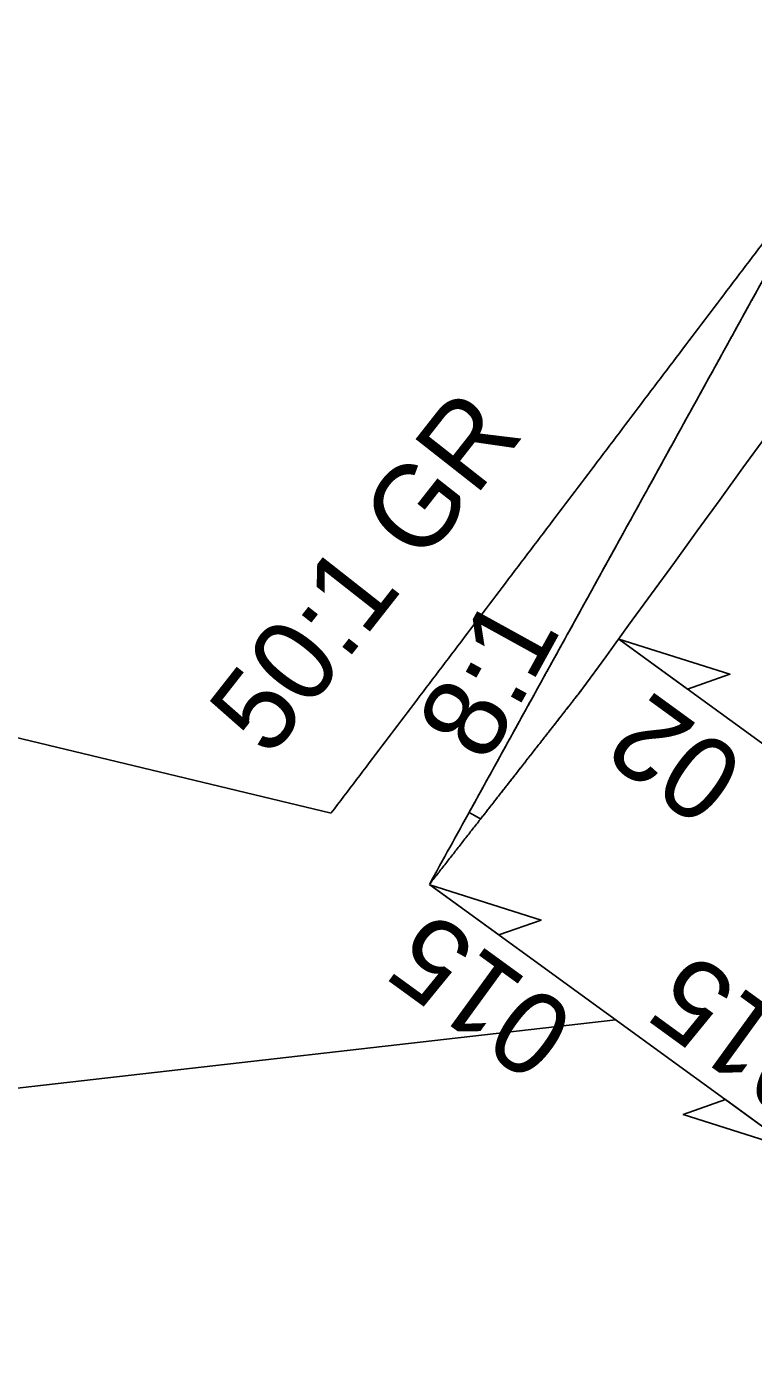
# Model space of a CAD drawing. Extents: x 1183930 to 1185370, y 573068 to 574871.
# Drawn here: x 1184207.5 to 1184246.9, y 573632.6 to 573704.9 of the extents above; entities that cross this region are included whole.
import ezdxf

# ---------------------------------------------------------------- set-up
doc = ezdxf.new("R2010")
doc.units = 0
for name, color, linetype in [('E_NCDOT_Vertical_Profile_Ground_Line', 7, 'Continuous'), ('P_NCDOT_Horizontal_Alignment', 7, 'Continuous'), ('P_NCDOT_Horizontal_Alignment_Tick_Large', 7, 'Continuous'), ('PC_COLUMN', 7, 'Continuous'), ('PC_OBJECT', 7, 'Continuous'), ('PC_PADFOOTING', 7, 'Continuous'), ('PC_SLAB', 7, 'Continuous'), ('PS_HATCH', 7, 'Continuous')]:
    doc.layers.add(name, color=color, linetype=linetype)

msp = doc.modelspace()

# ---------------------------------------------------------------- linework, layer by layer
at = {"layer": 'E_NCDOT_Vertical_Profile_Ground_Line'}
msp.add_open_spline([(1184229.343, 573658.378), (1184229.712, 573659.047), (1184230.451, 573660.384), (1184231.559, 573662.391), (1184232.666, 573664.397), (1184233.774, 573666.404), (1184234.881, 573668.41), (1184235.989, 573670.417), (1184237.096, 573672.423), (1184238.203, 573674.43), (1184239.311, 573676.436), (1184240.418, 573678.443), (1184241.525, 573680.45), (1184242.632, 573682.456), (1184243.739, 573684.463), (1184244.846, 573686.47), (1184245.953, 573688.477), (1184247.06, 573690.483), (1184248.166, 573692.49), (1184249.273, 573694.497), (1184250.379, 573696.504), (1184251.117, 573697.842), (1184251.486, 573698.511)], degree=3, dxfattribs=at)
msp.add_open_spline([(1184229.343, 573658.378), (1184229.712, 573659.047), (1184230.451, 573660.384), (1184231.559, 573662.391), (1184232.666, 573664.397), (1184233.774, 573666.404), (1184234.881, 573668.41), (1184235.989, 573670.417), (1184237.096, 573672.423), (1184238.203, 573674.43), (1184239.311, 573676.436), (1184240.418, 573678.443), (1184241.525, 573680.45), (1184242.632, 573682.456), (1184243.739, 573684.463), (1184244.846, 573686.47), (1184245.953, 573688.477), (1184247.06, 573690.483), (1184248.166, 573692.49), (1184249.273, 573694.497), (1184250.379, 573696.504), (1184251.117, 573697.842), (1184251.486, 573698.511)], degree=3, dxfattribs=at)
msp.add_open_spline([(1184229.343, 573658.378), (1184229.712, 573659.047), (1184230.451, 573660.384), (1184231.559, 573662.391), (1184232.666, 573664.397), (1184233.774, 573666.404), (1184234.881, 573668.41), (1184235.989, 573670.417), (1184237.096, 573672.423), (1184238.203, 573674.43), (1184239.311, 573676.436), (1184240.418, 573678.443), (1184241.525, 573680.45), (1184242.632, 573682.456), (1184243.739, 573684.463), (1184244.846, 573686.47), (1184245.953, 573688.477), (1184247.06, 573690.483), (1184248.166, 573692.49), (1184249.273, 573694.497), (1184250.379, 573696.504), (1184251.117, 573697.842), (1184251.486, 573698.511)], degree=3, dxfattribs=at)
at = {"layer": 'P_NCDOT_Horizontal_Alignment'}
msp.add_line((1184229.343, 573658.378), (1184249.41, 573643.786), dxfattribs=at)
msp.add_arc((1124762.272, 616900.028), 73527.16, 323.98763727, 324.09287436, dxfattribs=at)
msp.add_arc((1124762.272, 616900.028), 73527.16, 323.98763727, 324.09287436, dxfattribs=at)
msp.add_open_spline([(1184229.343, 573658.378), (1184229.482, 573658.555), (1184229.759, 573658.91), (1184230.176, 573659.441), (1184230.592, 573659.973), (1184231.008, 573660.505), (1184231.424, 573661.037), (1184231.841, 573661.568), (1184232.257, 573662.1), (1184232.673, 573662.632), (1184233.089, 573663.164), (1184233.506, 573663.695), (1184233.922, 573664.227), (1184234.338, 573664.759), (1184234.754, 573665.291), (1184235.17, 573665.823), (1184235.587, 573666.354), (1184236.003, 573666.886), (1184236.419, 573667.418), (1184236.835, 573667.95), (1184237.252, 573668.482), (1184237.529, 573668.836), (1184237.668, 573669.014)], degree=3, dxfattribs=at)
msp.add_open_spline([(1184229.343, 573658.378), (1184229.482, 573658.555), (1184229.759, 573658.91), (1184230.176, 573659.441), (1184230.592, 573659.973), (1184231.008, 573660.505), (1184231.424, 573661.037), (1184231.841, 573661.568), (1184232.257, 573662.1), (1184232.673, 573662.632), (1184233.089, 573663.164), (1184233.506, 573663.695), (1184233.922, 573664.227), (1184234.338, 573664.759), (1184234.754, 573665.291), (1184235.17, 573665.823), (1184235.587, 573666.354), (1184236.003, 573666.886), (1184236.419, 573667.418), (1184236.835, 573667.95), (1184237.252, 573668.482), (1184237.529, 573668.836), (1184237.668, 573669.014)], degree=3, dxfattribs=at)
at = {"layer": 'P_NCDOT_Horizontal_Alignment_Tick_Large'}
msp.add_open_spline([(1184224.019, 573662.249), (1184224.477, 573662.853), (1184225.393, 573664.061), (1184226.767, 573665.874), (1184228.141, 573667.687), (1184229.515, 573669.5), (1184230.888, 573671.313), (1184232.262, 573673.126), (1184233.635, 573674.939), (1184235.009, 573676.752), (1184236.382, 573678.565), (1184237.756, 573680.378), (1184239.129, 573682.191), (1184240.502, 573684.004), (1184241.875, 573685.817), (1184243.248, 573687.63), (1184244.621, 573689.444), (1184245.994, 573691.257), (1184247.367, 573693.07), (1184248.74, 573694.884), (1184250.113, 573696.697), (1184251.028, 573697.906), (1184251.486, 573698.511)], degree=3, dxfattribs=at)
msp.add_open_spline([(1184224.019, 573662.249), (1184224.477, 573662.853), (1184225.393, 573664.061), (1184226.767, 573665.874), (1184228.141, 573667.687), (1184229.515, 573669.5), (1184230.888, 573671.313), (1184232.262, 573673.126), (1184233.635, 573674.939), (1184235.009, 573676.752), (1184236.382, 573678.565), (1184237.756, 573680.378), (1184239.129, 573682.191), (1184240.502, 573684.004), (1184241.875, 573685.817), (1184243.248, 573687.63), (1184244.621, 573689.444), (1184245.994, 573691.257), (1184247.367, 573693.07), (1184248.74, 573694.884), (1184250.113, 573696.697), (1184251.028, 573697.906), (1184251.486, 573698.511)], degree=3, dxfattribs=at)
at = {"layer": 'PC_COLUMN'}
for points in [[(1184239.608, 573671.682), (1184245.637, 573669.771), (1184243.348, 573668.962)], [(1184229.374, 573658.354), (1184235.403, 573656.443), (1184233.115, 573655.634)], [(1184249.137, 573643.985), (1184243.108, 573645.896), (1184245.396, 573646.705)]]:
    msp.add_lwpolyline(points, close=True, dxfattribs=at)
at = {"layer": 'PC_OBJECT'}
msp.add_line((1184232.118, 573661.923), (1184231.491, 573662.269), dxfattribs=at)
msp.add_arc((1124762.272, 616900.028), 73527.16, 323.98763727, 324.09287436, dxfattribs=at)
for points in [[(1184244.108, 573685.132), (1184244.132, 573685.175), (1184244.156, 573685.219), (1184244.18, 573685.262), (1184244.277, 573685.438), (1184244.374, 573685.614), (1184244.471, 573685.789), (1184244.567, 573685.965), (1184244.664, 573686.141), (1184244.761, 573686.317), (1184244.858, 573686.492), (1184244.955, 573686.668), (1184245.052, 573686.844), (1184245.149, 573687.019), (1184245.246, 573687.195), (1184245.343, 573687.371), (1184245.44, 573687.547), (1184245.537, 573687.722), (1184245.634, 573687.898), (1184245.731, 573688.074), (1184245.828, 573688.25), (1184245.924, 573688.425), (1184246.021, 573688.601), (1184246.118, 573688.777), (1184246.215, 573688.953), (1184246.312, 573689.128), (1184246.409, 573689.304), (1184246.506, 573689.48), (1184246.603, 573689.655), (1184246.7, 573689.831), (1184246.797, 573690.007), (1184246.894, 573690.183), (1184246.991, 573690.358), (1184247.088, 573690.534), (1184247.184, 573690.71), (1184247.281, 573690.886), (1184247.378, 573691.061), (1184247.475, 573691.237), (1184247.572, 573691.413), (1184247.669, 573691.589), (1184247.766, 573691.764), (1184247.863, 573691.94), (1184247.96, 573692.116), (1184248.057, 573692.292), (1184248.154, 573692.467), (1184248.25, 573692.643), (1184248.347, 573692.819), (1184248.444, 573692.995), (1184248.541, 573693.17), (1184248.638, 573693.346), (1184248.735, 573693.522), (1184248.832, 573693.697), (1184248.929, 573693.873), (1184249.026, 573694.049), (1184249.123, 573694.225), (1184249.22, 573694.4), (1184249.316, 573694.576), (1184249.413, 573694.752), (1184249.51, 573694.928), (1184249.607, 573695.103), (1184249.704, 573695.279), (1184249.801, 573695.455), (1184249.898, 573695.631), (1184249.995, 573695.806), (1184250.092, 573695.982), (1184250.189, 573696.158), (1184250.285, 573696.334), (1184250.686, 573697.059), (1184251.086, 573697.785), (1184251.486, 573698.511)], [(1184236.727, 573671.754), (1184236.787, 573671.864), (1184236.848, 573671.973), (1184236.908, 573672.083), (1184237.005, 573672.259), (1184237.102, 573672.434), (1184237.199, 573672.61), (1184237.296, 573672.786), (1184237.393, 573672.962), (1184237.49, 573673.137), (1184237.587, 573673.313), (1184237.684, 573673.489), (1184237.781, 573673.664), (1184237.878, 573673.84), (1184237.975, 573674.016), (1184238.072, 573674.192), (1184238.169, 573674.367), (1184238.266, 573674.543), (1184238.363, 573674.719), (1184238.46, 573674.894), (1184238.557, 573675.07), (1184238.654, 573675.246), (1184238.751, 573675.422), (1184238.848, 573675.597), (1184238.945, 573675.773), (1184239.042, 573675.949), (1184239.139, 573676.124), (1184239.236, 573676.3), (1184239.332, 573676.476), (1184239.429, 573676.652), (1184239.526, 573676.827), (1184239.623, 573677.003), (1184239.72, 573677.179), (1184239.817, 573677.354), (1184239.914, 573677.53), (1184240.011, 573677.706), (1184240.108, 573677.882), (1184240.205, 573678.057), (1184240.302, 573678.233), (1184240.399, 573678.409), (1184240.496, 573678.585), (1184240.593, 573678.76), (1184240.69, 573678.936), (1184240.787, 573679.112), (1184240.884, 573679.287), (1184240.981, 573679.463), (1184241.078, 573679.639), (1184241.175, 573679.815), (1184241.272, 573679.99), (1184241.368, 573680.166), (1184241.465, 573680.342), (1184241.562, 573680.518), (1184241.659, 573680.693), (1184241.756, 573680.869), (1184241.853, 573681.045), (1184241.95, 573681.22), (1184242.047, 573681.396), (1184242.144, 573681.572), (1184242.241, 573681.748), (1184242.338, 573681.923), (1184242.435, 573682.099), (1184242.532, 573682.275), (1184242.629, 573682.45), (1184242.726, 573682.626), (1184242.823, 573682.802), (1184242.92, 573682.978), (1184243.017, 573683.153), (1184243.113, 573683.329), (1184243.21, 573683.505), (1184243.307, 573683.681), (1184243.404, 573683.856), (1184243.501, 573684.032), (1184243.598, 573684.208), (1184243.695, 573684.384), (1184243.792, 573684.559), (1184243.889, 573684.735), (1184243.962, 573684.867), (1184244.035, 573684.999), (1184244.108, 573685.132)], [(1184231.491, 573662.269), (1184231.551, 573662.378), (1184231.611, 573662.486), (1184231.671, 573662.595), (1184231.768, 573662.77), (1184231.865, 573662.946), (1184231.962, 573663.122), (1184232.059, 573663.297), (1184232.156, 573663.473), (1184232.253, 573663.649), (1184232.35, 573663.825), (1184232.447, 573664), (1184232.544, 573664.176), (1184232.641, 573664.352), (1184232.738, 573664.527), (1184232.835, 573664.703), (1184232.932, 573664.879), (1184233.029, 573665.055), (1184233.126, 573665.23), (1184233.223, 573665.406), (1184233.32, 573665.582), (1184233.417, 573665.757), (1184233.514, 573665.933), (1184233.611, 573666.109), (1184233.708, 573666.284), (1184233.805, 573666.46), (1184233.902, 573666.636), (1184233.999, 573666.812), (1184234.096, 573666.987), (1184234.193, 573667.163), (1184234.29, 573667.339), (1184234.387, 573667.514), (1184234.484, 573667.69), (1184234.581, 573667.866), (1184234.678, 573668.042), (1184234.775, 573668.217), (1184234.872, 573668.393), (1184234.969, 573668.569), (1184235.066, 573668.744), (1184235.163, 573668.92), (1184235.26, 573669.096), (1184235.357, 573669.272), (1184235.454, 573669.447), (1184235.551, 573669.623), (1184235.648, 573669.799), (1184235.745, 573669.974), (1184235.842, 573670.15), (1184235.939, 573670.326), (1184236.036, 573670.502), (1184236.133, 573670.677), (1184236.23, 573670.853), (1184236.326, 573671.029), (1184236.423, 573671.204), (1184236.52, 573671.38), (1184236.617, 573671.556), (1184236.654, 573671.622), (1184236.69, 573671.688), (1184236.727, 573671.754)], [(1184237.668, 573669.014), (1184237.593, 573668.918), (1184237.518, 573668.822), (1184237.443, 573668.726), (1184237.405, 573668.678), (1184237.368, 573668.63), (1184237.33, 573668.582), (1184237.293, 573668.534), (1184237.255, 573668.486), (1184237.218, 573668.439), (1184237.18, 573668.391), (1184237.143, 573668.343), (1184237.105, 573668.295), (1184237.068, 573668.247), (1184237.03, 573668.199), (1184236.993, 573668.151), (1184236.955, 573668.103), (1184236.918, 573668.055), (1184236.88, 573668.007), (1184236.843, 573667.959), (1184236.805, 573667.912), (1184236.768, 573667.864), (1184236.73, 573667.816), (1184236.693, 573667.768), (1184236.655, 573667.72), (1184236.618, 573667.672), (1184236.58, 573667.624), (1184236.543, 573667.576), (1184236.505, 573667.528), (1184236.468, 573667.48), (1184236.43, 573667.432), (1184236.393, 573667.385), (1184236.355, 573667.337), (1184236.318, 573667.289), (1184236.28, 573667.241), (1184236.243, 573667.193), (1184236.205, 573667.145), (1184236.168, 573667.097), (1184236.13, 573667.049), (1184236.093, 573667.001), (1184236.055, 573666.953), (1184236.018, 573666.905), (1184235.98, 573666.857), (1184235.943, 573666.81), (1184235.905, 573666.762), (1184235.868, 573666.714), (1184235.83, 573666.666), (1184235.793, 573666.618), (1184235.755, 573666.57), (1184235.718, 573666.522), (1184235.68, 573666.474), (1184235.643, 573666.426), (1184235.605, 573666.378), (1184235.568, 573666.33), (1184235.53, 573666.283), (1184235.493, 573666.235), (1184235.455, 573666.187), (1184235.418, 573666.139), (1184235.38, 573666.091), (1184235.343, 573666.043), (1184235.305, 573665.995), (1184235.268, 573665.947), (1184235.23, 573665.899), (1184235.193, 573665.851), (1184235.155, 573665.803), (1184235.118, 573665.756), (1184235.081, 573665.708), (1184235.043, 573665.66), (1184235.006, 573665.612), (1184234.968, 573665.564), (1184234.943, 573665.532), (1184234.918, 573665.5), (1184234.893, 573665.468)], [(1184234.893, 573665.468), (1184234.881, 573665.452), (1184234.868, 573665.436), (1184234.856, 573665.42), (1184234.818, 573665.372), (1184234.781, 573665.324), (1184234.743, 573665.276), (1184234.706, 573665.229), (1184234.668, 573665.181), (1184234.631, 573665.133), (1184234.593, 573665.085), (1184234.556, 573665.037), (1184234.518, 573664.989), (1184234.481, 573664.941), (1184234.443, 573664.893), (1184234.406, 573664.845), (1184234.368, 573664.797), (1184234.331, 573664.749), (1184234.293, 573664.702), (1184234.256, 573664.654), (1184234.218, 573664.606), (1184234.181, 573664.558), (1184234.143, 573664.51), (1184234.106, 573664.462), (1184234.068, 573664.414), (1184234.031, 573664.366), (1184233.993, 573664.318), (1184233.956, 573664.27), (1184233.918, 573664.222), (1184233.881, 573664.175), (1184233.843, 573664.127), (1184233.806, 573664.079), (1184233.768, 573664.031), (1184233.731, 573663.983), (1184233.693, 573663.935), (1184233.656, 573663.887), (1184233.618, 573663.839), (1184233.581, 573663.791), (1184233.543, 573663.743), (1184233.506, 573663.695), (1184233.468, 573663.648), (1184233.431, 573663.6), (1184233.393, 573663.552), (1184233.356, 573663.504), (1184233.318, 573663.456), (1184233.281, 573663.408), (1184233.243, 573663.36), (1184233.206, 573663.312), (1184233.168, 573663.264), (1184233.131, 573663.216), (1184233.093, 573663.168), (1184233.056, 573663.121), (1184233.018, 573663.073), (1184232.981, 573663.025), (1184232.943, 573662.977), (1184232.906, 573662.929), (1184232.868, 573662.881), (1184232.831, 573662.833), (1184232.793, 573662.785), (1184232.756, 573662.737), (1184232.718, 573662.689), (1184232.681, 573662.641), (1184232.643, 573662.594), (1184232.606, 573662.546), (1184232.568, 573662.498), (1184232.531, 573662.45), (1184232.493, 573662.402), (1184232.456, 573662.354), (1184232.418, 573662.306), (1184232.381, 573662.258), (1184232.343, 573662.21), (1184232.306, 573662.162), (1184232.268, 573662.115), (1184232.231, 573662.067), (1184232.193, 573662.019), (1184232.156, 573661.971), (1184232.143, 573661.955), (1184232.131, 573661.939), (1184232.118, 573661.923)]]:
    msp.add_open_spline(points, degree=3, dxfattribs=at)
at = {"layer": 'PC_PADFOOTING'}
msp.add_line((1184148.901, 573680.295), (1184224.007, 573662.233), dxfattribs=at)
at = {"layer": 'PC_SLAB'}
msp.add_line((1184259.021, 573657.572), (1184239.608, 573671.682), dxfattribs=at)
at = {"layer": 'PS_HATCH'}
msp.add_line((1184239.46, 573651.022), (1184077.159, 573632.561), dxfattribs=at)

# ---------------------------------------------------------------- texts
at = {"layer": 'PC_PADFOOTING'}
for s, rotation, p in [('50:1 GR', 51.8439, (1184220.665, 573665.153)), ('8:1', 61.11274, (1184232.458, 573664.83))]:
    msp.add_text(s, height=4.5, rotation=rotation, dxfattribs=at).set_placement(p)
at = {"layer": 'PC_SLAB'}
for s, p in [('02', (1184246.699, 573665)), ('015', (1184237.5, 573651.155)), ('015', (1184251.669, 573648.918))]:
    msp.add_text(s, height=4.5, rotation=143.97712, dxfattribs=at).set_placement(p)

doc.saveas('drawing.dxf')
